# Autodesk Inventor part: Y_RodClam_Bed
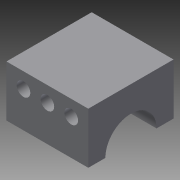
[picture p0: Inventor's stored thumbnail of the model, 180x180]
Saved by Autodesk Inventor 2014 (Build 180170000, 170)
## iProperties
Created: 2013-12
Part Number: Y_RodClam_Bed
Material: Generic
Document SubType Name: Modeling
Designer: Bram
Density: 1 g/cm^3
Appearance: Default
Author: Bram
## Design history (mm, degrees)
sketch "Sketch1"
  geometry: L1 (7.5, 0)-(12.5, 0); L2 (12.5, 0)-(12.5, 15); L3 (12.5, 15)-(-12.5, 15); L4 (-12.5, 15)-(-12.5, 0); L5 (-12.5, 0)-(-7.5, 0); A1 r 7.5 centre (0, 0) between (7.5, 0) and (-7.5, 0); 1 further point
  constraints: 10 end point, 2 parallel, 2 point on circle, 1 centre point, 1 coincident, 1 collinear, 1 horizontal, 1 perpendicular
  dimensions: "d0" = 15 diameter of A1; "d1" = 12.5 distance of A1.centre L1.end; "d2" = 15 distance of L1.end L2.end; "d3" = 25 distance of L2.end L3.end
extrude "Extrusion1" new body sketch "Sketch1" distance "d4" = 24; taper "d5" = 0 deg
sketch "Sketch2"
  geometry: C1 r 2 at (5, 10.5); C2 r 2 at (12, 10.5); C3 r 2 at (19, 10.5)
  constraints: 3 centre point
  dimensions: "d11" = 4 diameter of C3
extrude "Extrusion2" cut sketch "Sketch2" distance "d12" = 25; taper "d13" = 0 deg
body "Solid1"
